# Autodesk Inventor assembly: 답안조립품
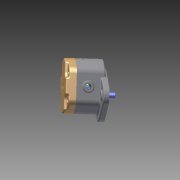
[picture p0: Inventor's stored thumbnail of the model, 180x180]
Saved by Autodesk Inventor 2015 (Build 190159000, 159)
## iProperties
Created: 2025-11
Part Number: 답안조립품
Document SubType Name: Assembly
Designer: user
Author: user
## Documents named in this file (11)
- C:\Users\user\Desktop\751103V1006\답안조립품.iam
- C:\Users\user\Desktop\751103V1006\가져온 구성요소\3자 실링\3자 실링.ipt
- C:\Users\user\Desktop\751103V1006\가져온 구성요소\6각 구멍붙이 볼트 M6x16\6각 구멍붙이 볼트 M6x16.ipt
- C:\Users\user\Desktop\751103V1006\가져온 구성요소\DU 부시\DU 부시.ipt
- C:\Users\user\Desktop\751103V1006\가져온 구성요소\가이드 블록\가이드 블록.ipt
- C:\Users\user\Desktop\751103V1006\가져온 구성요소\구동기어\구동기어.ipt
- C:\Users\user\Desktop\751103V1006\본체.ipt
- C:\Users\user\Desktop\751103V1006\가져온 구성요소\스퍼기어\스퍼기어.ipt
- C:\Users\user\Desktop\751103V1006\가져온 구성요소\실링\실링.ipt
- C:\Users\user\Desktop\751103V1006\가져온 구성요소\오일 실 16 30 7\오일 실 16 30 7.ipt
- C:\Users\user\Desktop\751103V1006\가져온 구성요소\커버\커버.ipt
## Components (11 placed, 5 different names)
1. 3자 실링:1
2. 6각 구멍붙이 볼트 M6x16:1
3. DU 부시:1
4. 가이드 블록:1
5. 구동기어:1
6. DU 부시:2
7. DU 부시:3
8. DU 부시:4
9. 6각 구멍붙이 볼트 M6x16:2
10. 6각 구멍붙이 볼트 M6x16:3
11. 6각 구멍붙이 볼트 M6x16:4
